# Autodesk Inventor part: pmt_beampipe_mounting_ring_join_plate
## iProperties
Shininess: 64.0
Length Units: 11269
Angle Units: 11279
Time Units: 11290
Mass Units: 11283
Length Display Precision: 3
Angle Display Precision: 2
Compacted: True
Part Number: pmt_beampipe_mounting_ring_join_plate
Document SubType Name: Modeling
Created: 2004-08
Designer: John Blackburn
Manufacturer: Standard
Standards Organization: Custom
Material: Aluminum-6061
Density: 0.0
Volumn: 0.0
Area: 0.0
PropertySet Name: Model Information
Control State: 0
Master: False
Checked Out: False
Author: John Blackburn
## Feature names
1. Extrusion1
2. Hole1
